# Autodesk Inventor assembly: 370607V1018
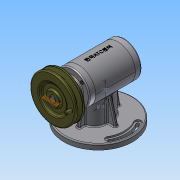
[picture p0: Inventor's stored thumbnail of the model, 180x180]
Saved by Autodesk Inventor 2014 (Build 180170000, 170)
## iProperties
Created: 2017-06
Part Number: 370607V1018
Document SubType Name: Assembly
Designer: NET
Author: NET
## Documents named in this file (15)
- C:\Users\NET\Desktop\370607V1018\370607V1018.iam
- C:\Users\NET\Desktop\370607V1018\본체.ipt
- C:\Users\NET\Desktop\370607V1018\본체커버.ipt
- C:\Users\NET\Desktop\370607V1018\앞커버.ipt
- C:\Users\NET\Desktop\370607V1018\볼트 M3x0.5x8.ipt
- C:\Users\NET\Desktop\370607V1018\오일실 12 22 7.ipt
- C:\Users\NET\Desktop\370607V1018\베어링 6201.ipt
- C:\Users\NET\Desktop\370607V1018\뒤커버.ipt
- C:\Users\NET\Desktop\370607V1018\베어링 6202.ipt
- C:\Users\NET\Desktop\370607V1018\편심축.ipt
- C:\Users\NET\Desktop\370607V1018\키 4 x 4 x 18.ipt
- C:\Users\NET\Desktop\370607V1018\V-벨트풀리.ipt
- C:\Users\NET\Desktop\370607V1018\멈춤나사 M3x8.ipt
- C:\Users\NET\Desktop\370607V1018\슬라이드.ipt
- C:\Users\NET\Desktop\370607V1018\스프링-[가변].ipt
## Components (1 placed, 1 different names)
1. V-벨트풀리:1 — 강체:1
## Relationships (1: WeldJoint 1)
- 강체:1 [WeldJoint]: V-벨트풀리:1
